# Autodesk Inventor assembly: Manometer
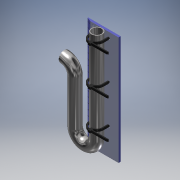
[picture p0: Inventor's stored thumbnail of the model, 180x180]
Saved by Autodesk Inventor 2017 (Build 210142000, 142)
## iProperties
Created: 2020-04
Part Number: Manometer
Description: STEP AP214
Document SubType Name: Assembly
Designer: user
Sending System: SolidWorks 2018
Preprocessor: SwSTEP 2.0
Title: Manometer.STEP
Revision Number: ANY
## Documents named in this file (4)
- C:\Users\user\Documents\Inventor\Home Ventilator CPAP\Manometer.iam
- C:\Users\user\Documents\Inventor\Home Ventilator CPAP\Ruler.ipt
- C:\Users\user\Documents\Inventor\Home Ventilator CPAP\Tube.ipt
- C:\Users\user\Documents\Inventor\Home Ventilator CPAP\ziptie.ipt
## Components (5 placed, 5 different names)
1. Ruler_1
2. Tube_2
3. ziptie_3
4. ziptie_4
5. ziptie_5
